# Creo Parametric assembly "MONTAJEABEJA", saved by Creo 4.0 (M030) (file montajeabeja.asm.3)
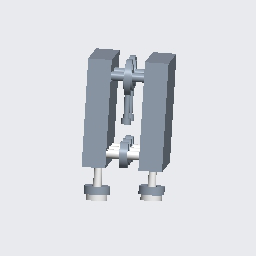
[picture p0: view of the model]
Units: millimeter Newton Second (mmNs); MM, TONNE, SECS

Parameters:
  MODELED_BY = "aj"

Created from: MMNS_ASM_DESIGN.ASM

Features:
  1. datum plane "ASM_RIGHT"
  2. datum plane "ASM_TOP"
  3. datum plane "ASM_FRONT"
  4. coordinate system
  5. component "LADOSUNIONESABEJA"
  6. component "EJECENTROABEJA"
  7. component "EJECENTROABEJA"
  8. component "EJECENTROABEJA"
  9. component "LADOSUNIONESABEJA"
  10. component "EJELATERALABEJA"
  11. component "EJELATERALABEJA"
  12. component "EJERUEDASCENTROABEJA"
  13. component "RODAMIENTOABEJA"
  14. component "SOPORTEPESO"
  15. component "EJERUEDASCENTROABEJA"
  16. component "RODAMIENTOABEJA"
  17. component "SOPORTEPESO"

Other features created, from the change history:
  component "LADOSUNIONESABEJA.PRT"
